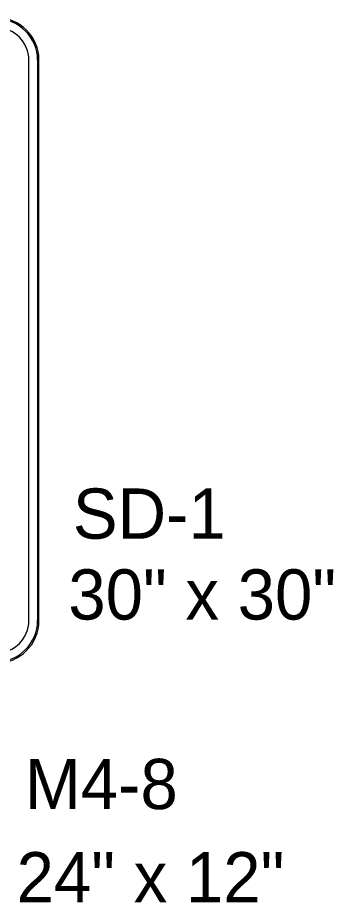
# Model space of a CAD drawing. Extents: x 2157572 to 5059327, y 715220 to 1674494.
# Drawn here: x 2166593 to 2166777, y 721021 to 721535 of the extents above; entities that cross this region are included whole.
import ezdxf

# ---------------------------------------------------------------- set-up
doc = ezdxf.new("R2010")
doc.units = 0
for name, color, linetype in [('Level 56', 7, 'Continuous'), ('Map Preparation County Base Location Boundary Shape', 7, 'Continuous'), ('Map Preparation County Base StatePlane Tick Mark', 7, 'Continuous'), ('Map Preparation County Inset Cut Line', 7, 'Continuous')]:
    doc.layers.add(name, color=color, linetype=linetype)

msp = doc.modelspace()

# ---------------------------------------------------------------- linework, layer by layer
at = {"layer": 'Map Preparation County Base Location Boundary Shape'}
for p, q in [((2166599.7, 721184.29), (2166599.7, 721510.08)), ((2166605.56, 721184.29), (2166605.56, 721510.08))]:
    msp.add_line(p, q, dxfattribs=at)
for centre, radius, start, end in [((2166580.95, 721510.08), 24.61, 0, 90), ((2166580.95, 721510.08), 18.75, 0, 90), ((2166580.95, 721184.29), 18.75, 270, 0), ((2166580.95, 721184.29), 24.61, 270, 0)]:
    msp.add_arc(centre, radius, start, end, dxfattribs=at)
at = {"layer": 'Map Preparation County Base StatePlane Tick Mark'}
for p, q in [((2166599.7, 721184.29), (2166599.7, 721510.08)), ((2166605.56, 721184.29), (2166605.56, 721510.08))]:
    msp.add_line(p, q, dxfattribs=at)
for centre, radius, start, end in [((2166580.95, 721510.08), 24.61, 0, 90), ((2166580.95, 721510.08), 18.75, 0, 90), ((2166580.95, 721184.29), 18.75, 270, 0), ((2166580.95, 721184.29), 24.61, 270, 0)]:
    msp.add_arc(centre, radius, start, end, dxfattribs=at)
at = {"layer": 'Map Preparation County Inset Cut Line'}
for p, q in [((2166599.7, 721184.29), (2166599.7, 721510.08)), ((2166604.78, 721510.08), (2166604.78, 721184.29)), ((2166605.56, 721184.29), (2166605.56, 721510.08)), ((2166605.56, 721184.29), (2166605.56, 721510.08))]:
    msp.add_line(p, q, dxfattribs=at)
for centre, radius, start, end in [((2166580.95, 721510.08), 24.61, 0, 90), ((2166580.95, 721510.08), 24.61, 0, 90), ((2166580.95, 721510.08), 23.83, 0, 90), ((2166580.95, 721510.08), 18.75, 0, 90), ((2166580.95, 721184.29), 24.61, 270, 0), ((2166580.95, 721184.29), 18.75, 270, 0), ((2166580.95, 721184.29), 24.61, 270, 0), ((2166580.95, 721184.29), 23.83, 270, 0)]:
    msp.add_arc(centre, radius, start, end, dxfattribs=at)

# ---------------------------------------------------------------- texts
at = {"layer": 'Level 56'}
for s, p in [('SD-1', (2166625.28, 721231.93)), ('30" x 30"', (2166622.66, 721184.93)), ('M4-8', (2166597.39, 721074.81)), ('24" x 12"', (2166592.58, 721020.62))]:
    msp.add_text(s, height=29.18, rotation=360, dxfattribs=at).set_placement(p)

doc.saveas('drawing.dxf')
